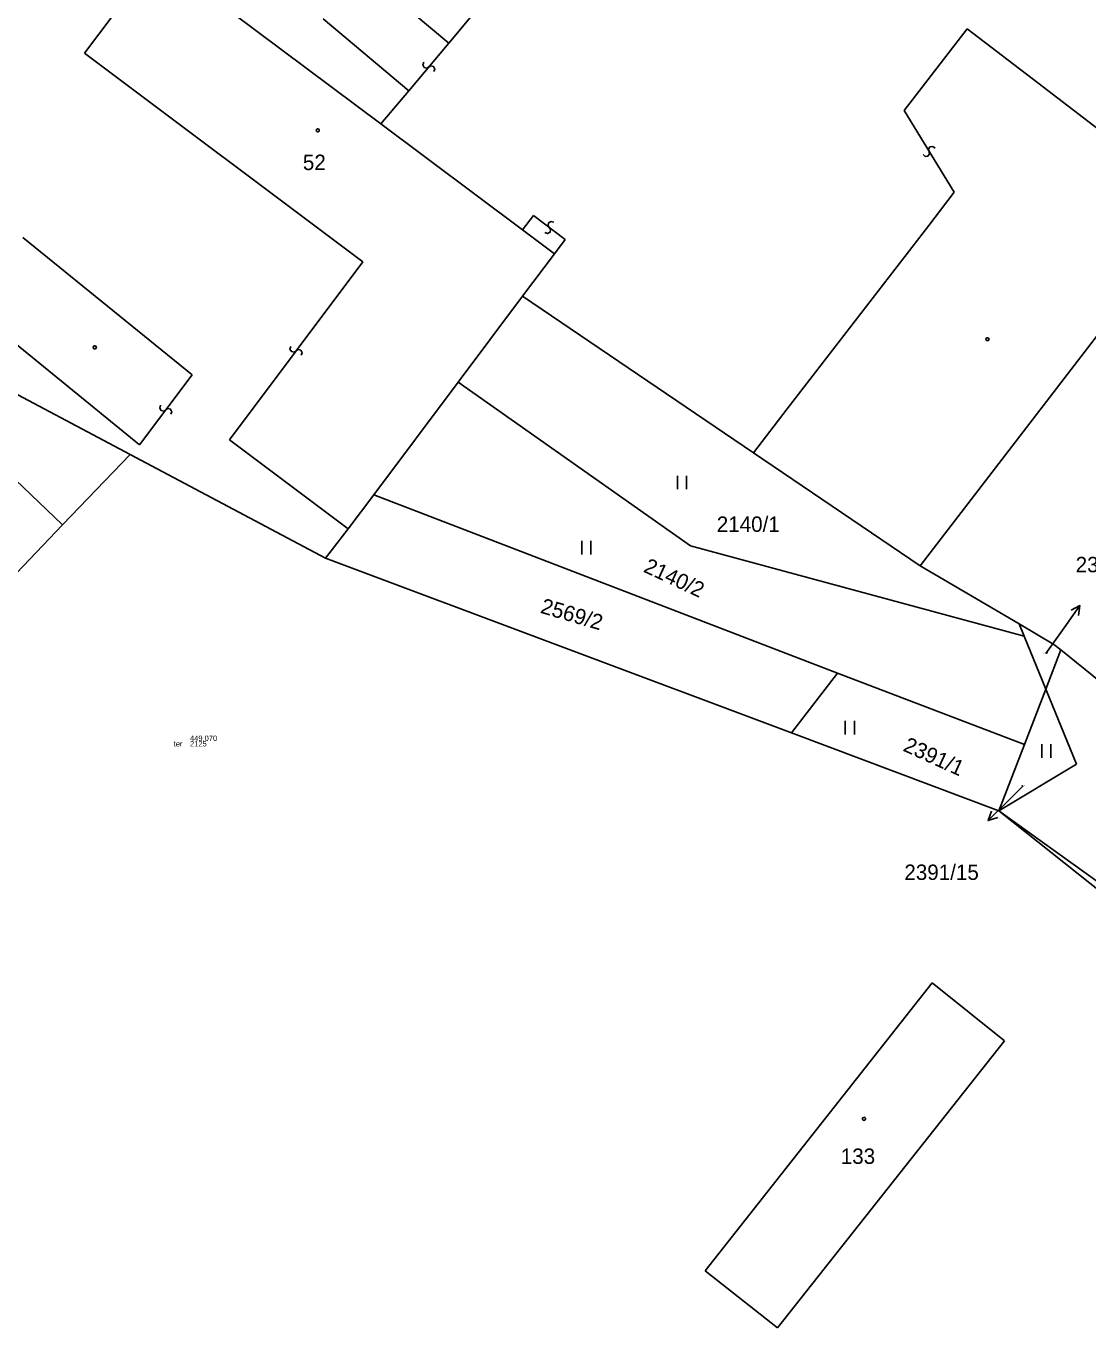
# Model space of a CAD drawing. Extents: x -747792 to -745414, y -1093712 to -1091463.
# Drawn here: x -746698 to -746639.4, y -1093219.2 to -1093147.3 of the extents above; entities that cross this region are included whole.
import ezdxf

# ---------------------------------------------------------------- set-up
doc = ezdxf.new("R2010")
doc.units = 0
for name, color, linetype in [('Budovy', 7, 'Continuous'), ('Doplňkové značky', 7, 'Continuous'), ('Hladina', 7, 'Continuous'), ('Koleje_dopravní prvky', 7, 'Continuous'), ('Kultury', 7, 'Continuous'), ('Ploty_opěrné zdi', 7, 'Continuous'), ('Rozhraní ploch', 7, 'Continuous'), ('Stromy_porost', 7, 'Continuous'), ('Výškopis', 7, 'Continuous')]:
    doc.layers.add(name, color=color, linetype=linetype)

msp = doc.modelspace()

# ---------------------------------------------------------------- linework, layer by layer
at = {"layer": 'Budovy'}
for points in [[(-746662.04, -1093172.13), (-746662.04, -1093172.88)], [(-746661.54, -1093172.88), (-746661.54, -1093172.13)], [(-746667.32, -1093175.73), (-746667.32, -1093176.48)], [(-746666.82, -1093176.48), (-746666.82, -1093175.73)], [(-746652.78, -1093185.66), (-746652.78, -1093186.41)], [(-746652.28, -1093186.41), (-746652.28, -1093185.66)], [(-746641.93, -1093186.96), (-746641.93, -1093187.71)], [(-746641.43, -1093187.71), (-746641.43, -1093186.96)]]:
    msp.add_lwpolyline(points, dxfattribs=at)
at = {"layer": 'Doplňkové značky'}
for points in [[(-746639.831, -1093179.297), (-746640.7, -1093180.52)], [(-746640.325, -1093179.56), (-746639.831, -1093179.297), (-746639.917, -1093179.85)], [(-746641.72, -1093181.95), (-746640.7, -1093180.52)], [(-746642.96, -1093189.26), (-746643.83, -1093190.12)], [(-746644.898, -1093191.174), (-746643.83, -1093190.12)], [(-746644.366, -1093191), (-746644.898, -1093191.174), (-746644.717, -1093190.644)]]:
    msp.add_lwpolyline(points, dxfattribs=at)
at = {"layer": 'Hladina'}
msp.add_line((-746688.94, -1093186.78), (-746688.94, -1093186.78), dxfattribs=at)
at = {"layer": 'Kultury'}
for points in [[(-746694.77, -1093148.8), (-746690.76, -1093143.45)], [(-746674.66, -1093148.24), (-746679.39, -1093144.27)], [(-746674.66, -1093148.24), (-746673.07, -1093146.35)], [(-746646.05, -1093147.46), (-746649.54, -1093151.96)], [(-746642.16, -1093150.44), (-746646.05, -1093147.46)], [(-746676.87, -1093150.87), (-746674.66, -1093148.24)], [(-746679.41, -1093160.32), (-746694.77, -1093148.8)], [(-746676.036, -1093149.295), (-746676.094, -1093149.441), (-746676.014, -1093149.587), (-746675.866, -1093149.62), (-746675.646, -1093149.492), (-746675.501, -1093149.536), (-746675.435, -1093149.683), (-746675.494, -1093149.815)], [(-746634.91, -1093156), (-746642.16, -1093150.44)], [(-746649.54, -1093151.96), (-746646.77, -1093156.48)], [(-746647.822, -1093154.045), (-746647.943, -1093153.944), (-746648.107, -1093153.973), (-746648.185, -1093154.104), (-746648.132, -1093154.353), (-746648.22, -1093154.477), (-746648.38, -1093154.493), (-746648.488, -1093154.395)], [(-746648.17, -1093158.31), (-746646.77, -1093156.48)], [(-746670.59, -1093158.56), (-746669.99, -1093157.76)], [(-746669.99, -1093157.76), (-746668.23, -1093159.08)], [(-746668.865, -1093158.135), (-746669.015, -1093158.085), (-746669.156, -1093158.173), (-746669.181, -1093158.323), (-746669.04, -1093158.535), (-746669.076, -1093158.683), (-746669.219, -1093158.757), (-746669.355, -1093158.705)], [(-746655.99, -1093168.44), (-746648.17, -1093158.31)], [(-746688.83, -1093166.55), (-746698.17, -1093158.98)], [(-746668.83, -1093159.88), (-746668.23, -1093159.08)], [(-746686.77, -1093170.14), (-746679.41, -1093160.32)], [(-746691.73, -1093170.42), (-746701.35, -1093162.58)], [(-746683.375, -1093164.985), (-746683.425, -1093165.135), (-746683.337, -1093165.276), (-746683.187, -1093165.301), (-746682.975, -1093165.16), (-746682.827, -1093165.196), (-746682.753, -1093165.339), (-746682.805, -1093165.475)], [(-746691.73, -1093170.42), (-746688.83, -1093166.55)], [(-746690.565, -1093168.24), (-746690.615, -1093168.39), (-746690.527, -1093168.531), (-746690.377, -1093168.556), (-746690.165, -1093168.415), (-746690.017, -1093168.451), (-746689.943, -1093168.594), (-746689.995, -1093168.73)], [(-746655.99, -1093168.44), (-746657.85, -1093170.86)], [(-746686.77, -1093170.14), (-746680.21, -1093175.06)]]:
    msp.add_lwpolyline(points, dxfattribs=at)
at = {"layer": 'Ploty_opěrné zdi'}
for points in [[(-746681.89, -1093152.975), (-746681.84, -1093152.985), (-746681.815, -1093153.03), (-746681.805, -1093153.06), (-746681.815, -1093153.105), (-746681.855, -1093153.14), (-746681.89, -1093153.145), (-746681.935, -1093153.13), (-746681.965, -1093153.1), (-746681.975, -1093153.06), (-746681.965, -1093153.015), (-746681.925, -1093152.98)], [(-746694.155, -1093164.965), (-746694.11, -1093165.04), (-746694.155, -1093165.115), (-746694.245, -1093165.115), (-746694.29, -1093165.04), (-746694.245, -1093164.965)], [(-746644.895, -1093164.515), (-746644.85, -1093164.59), (-746644.895, -1093164.665), (-746644.985, -1093164.665), (-746645.03, -1093164.59), (-746644.985, -1093164.515)], [(-746651.75, -1093207.555), (-746651.7, -1093207.565), (-746651.675, -1093207.61), (-746651.665, -1093207.64), (-746651.675, -1093207.685), (-746651.715, -1093207.72), (-746651.75, -1093207.725), (-746651.795, -1093207.71), (-746651.825, -1093207.68), (-746651.835, -1093207.64), (-746651.825, -1093207.595), (-746651.785, -1093207.56)]]:
    msp.add_lwpolyline(points, close=True, dxfattribs=at)
at = {"layer": 'Stromy_porost'}
for points in [[(-746690.76, -1093143.45), (-746678.41, -1093152.7)], [(-746681.6, -1093146.9), (-746676.87, -1093150.87)], [(-746676.87, -1093150.87), (-746678.41, -1093152.7)], [(-746678.41, -1093152.7), (-746670.59, -1093158.56)], [(-746633.36, -1093157.2), (-746648.65, -1093177.1)], [(-746670.59, -1093158.56), (-746668.83, -1093159.88)], [(-746670.59, -1093162.22), (-746668.83, -1093159.88)], [(-746670.59, -1093162.22), (-746674.14, -1093166.96)], [(-746657.85, -1093170.86), (-746670.59, -1093162.22)], [(-746692.24, -1093170.95), (-746700.22, -1093166.72)], [(-746674.14, -1093166.96), (-746678.8, -1093173.18)], [(-746674.14, -1093166.96), (-746661.33, -1093176)], [(-746702.04, -1093169.05), (-746695.97, -1093174.85)], [(-746695.97, -1093174.85), (-746692.24, -1093170.95)], [(-746692.24, -1093170.95), (-746681.46, -1093176.68)], [(-746657.85, -1093170.86), (-746648.65, -1093177.1)], [(-746678.8, -1093173.18), (-746680.21, -1093175.06)], [(-746678.8, -1093173.18), (-746653.21, -1093183.03)], [(-746695.97, -1093174.85), (-746704.33, -1093183.6)], [(-746680.21, -1093175.06), (-746681.46, -1093176.68)], [(-746661.33, -1093176), (-746642.91, -1093180.99)], [(-746655.75, -1093186.33), (-746681.46, -1093176.68)], [(-746648.65, -1093177.1), (-746643.19, -1093180.31)], [(-746643.19, -1093180.31), (-746641.27, -1093181.44)], [(-746642.91, -1093180.99), (-746643.19, -1093180.31)], [(-746641.71, -1093183.92), (-746642.91, -1093180.99)], [(-746641.27, -1093181.44), (-746640.88, -1093181.75)], [(-746640.88, -1093181.75), (-746641.71, -1093183.92)], [(-746640.88, -1093181.75), (-746635.6, -1093186.02)], [(-746653.21, -1093183.03), (-746655.75, -1093186.33)], [(-746642.89, -1093186.97), (-746653.21, -1093183.03)], [(-746641.71, -1093183.92), (-746642.89, -1093186.97)], [(-746641.71, -1093183.92), (-746640.02, -1093188.06)], [(-746644.3, -1093190.63), (-746655.75, -1093186.33)], [(-746642.89, -1093186.97), (-746644.3, -1093190.63)], [(-746644.3, -1093190.63), (-746640.02, -1093188.06)], [(-746623.42, -1093207.26), (-746644.3, -1093190.63)], [(-746636.24, -1093196.43), (-746644.3, -1093190.63)], [(-746647.98, -1093200.14), (-746660.51, -1093216.04)], [(-746647.98, -1093200.14), (-746644, -1093203.33)], [(-746644, -1093203.33), (-746656.53, -1093219.19)], [(-746656.53, -1093219.19), (-746660.51, -1093216.04)]]:
    msp.add_lwpolyline(points, dxfattribs=at)

# ---------------------------------------------------------------- texts
at = {"layer": 'Doplňkové značky'}
for s, p in [('2391/16', (-746640.068, -1093177.46)), ('2391/15', (-746649.522, -1093194.45))]:
    msp.add_text(s, height=0.85, dxfattribs=at).set_placement(p)
at = {"layer": 'Koleje_dopravní prvky'}
for s, height, p in [('52', 0.85, (-746682.713, -1093155.25)), ('2140/1', 0.85, (-746659.873, -1093175.23)), ('2391/16', 0.05, (-746641.846, -1093181.95)), ('2391/15', 0.05, (-746643.087, -1093189.26)), ('133', 0.85, (-746653.03, -1093210.13))]:
    msp.add_text(s, height=height, dxfattribs=at).set_placement(p)
for s, rotation, p in [('2140/2', 335.00842, (-746663.969, -1093177.416)), ('2569/2', 343.66009, (-746669.651, -1093179.693)), ('2391/1', 335.58138, (-746649.643, -1093187.299))]:
    msp.add_text(s, height=0.85, rotation=rotation, dxfattribs=at).set_placement(p)
at = {"layer": 'Rozhraní ploch'}
for s, p in [(' ter', (-746689.956, -1093187.08)), ('2125', (-746688.94, -1093187.08))]:
    msp.add_text(s, height=0.3, dxfattribs=at).set_placement(p)
at = {"layer": 'Výškopis'}
msp.add_text('449,070', height=0.3, dxfattribs=at).set_placement((-746688.94, -1093186.78))

doc.saveas('drawing.dxf')
